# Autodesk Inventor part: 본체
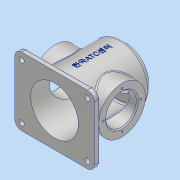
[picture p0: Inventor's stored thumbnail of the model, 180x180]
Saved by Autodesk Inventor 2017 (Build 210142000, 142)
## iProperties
Part Number: 본체
Material: 알루미늄 6061
Document SubType Name: Modeling
Designer: MRC
Density: 2.7 g/cm^3
Appearance: 알루미늄 - 평지
Mass: 1232.9 g
Surface Area: 1063.64 cm^2
Volume: 456.631 cm^3
Author: MRC
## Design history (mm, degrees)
sketch "스케치1"
  geometry: C1 r 50 at (0, 0); 1 further point
  constraints: 1 centre point, 1 coincident
  dimensions: "d0" = 100 diameter of C1
extrude "돌출1" new body sketch "스케치1" stored distance "d1" = 120; taper "d2" = 0 deg
sketch "스케치2"
  geometry: C1 r 41 at (0, 0); 1 further point
  constraints: 1 centre point, 1 coincident
  dimensions: "d3" = 82 diameter of C1
extrude "돌출2" join sketch "스케치2" distance "d4" = 5; taper "d5" = 0 deg
sketch "스케치3"
  geometry: L1 (70, -60)-(-70, -60); L2 (-70, -60)-(-70, 60); L3 (-70, 60)-(70, 60); L4 (70, 60)-(70, -60); L5 (70, -60)-(-70, 60); L6 (-70, -60)-(70, 60); 1 further point
  constraints: 12 end point, 2 midpoint, 2 parallel, 1 horizontal, 1 perpendicular
  dimensions: "d6" = 140 distance of L2.end L3.end; "d7" = 120 distance of L1.end L2.end
extrude "돌출3" join sketch "스케치3" distance "d8" = 10; taper "d9" = 0 deg
node "작업 평면1"
sketch "스케치4"
  geometry: C1 r 41 at (0, 0); 1 further point
  constraints: 1 centre point, 1 coincident
  dimensions: "d11" = 82 diameter of C1
extrude "돌출4" join sketch "스케치4" stored distance "d12" = 10; taper "d13" = 0 deg
sketch "스케치5"
  geometry: C1 r 42 at (0, 0); 1 further point
  constraints: 1 centre point, 1 coincident
  dimensions: "d14" = 84 diameter of C1
extrude "돌출5" cut sketch "스케치5" distance "d15" = 112; taper "d16" = 0 deg
sketch "스케치6"
  geometry: C1 r 27 at (0, 0); 1 further point
  constraints: 1 centre point, 1 coincident
  dimensions: "d17" = 54 diameter of C1
extrude "돌출6" cut sketch "스케치6" distance "d18" = 13; taper "d19" = 0 deg
sketch "스케치7"
  geometry: 2 further points
  constraints: 1 horizontal alignment
  dimensions: "d20" = 33 distance of point (0, 0) point (-33, 0)
hole "구멍1" sketch "스케치7" at (-33, 0) diameter "d21" = 3.242; stored, may be unused: countersink angle "d25" = 90 deg, drill point angle "d27" = 118 deg; dims "d22" = 8, "d23" = 4, "d24" = 2, "d26" = 10
sketch "스케치8"
  geometry: 2 further points
  constraints: 1 vertical alignment
  dimensions: "d28" = 33 distance of point (0, 0) point (0, 33)
hole "구멍2" sketch "스케치8" at (0, 33) diameter "d29" = 3.242; stored, may be unused: countersink angle "d33" = 90 deg, drill point angle "d35" = 118 deg; dims "d30" = 8, "d31" = 4, "d32" = 2, "d34" = 10
sketch "스케치9"
  geometry: C1 r 27 at (0, 0); 1 further point
  constraints: 1 centre point, 1 coincident
  dimensions: "d36" = 54 diameter of C1
extrude "돌출7" cut sketch "스케치9" stored distance "d37" = 13; taper "d38" = 0 deg
chamfer "모따기1" distance "d45" = 2; stored, may be unused: second distance "d46" = 2, angle "d47" = 45 deg
fillet "모깎기1" dims "d48" = 12
fillet "모깎기2" dims "d49" = 3
fillet "모깎기3" dims "d50" = 6
fillet "모깎기4" dims "d51" = 3
node "작업 평면2"
sketch "스케치10"
  geometry: L1 (-58, -60)-(58, -60) reference; 2 further points
  constraints: 1 vertical alignment, 1 other
  dimensions: "d53" = 66 distance from line of point (0, 6) L1
feature "엠보싱1" sketch "스케치10" dims "d11" = 82, "d54" = 0.5, "d55" = 0
sketch "스케치11"
  geometry: C1 r 4.5 at (-58, 48); A1 r 12 centre (-58, 48) between (-58, 60) and (-70, 48) reference; 1 further point
  constraints: 1 centre point, 1 concentric
  dimensions: "d56" = 9 diameter of C1
extrude "돌출8" cut sketch "스케치11" stored distance "d57" = 13; taper "d58" = 0 deg
node "솔리드1"
pattern_circular "원형 패턴1" dims angle "d40" = 360 deg
pattern_circular "원형 패턴2" dims angle "d43" = 360 deg
mirror "미러1"
mirror "미러2"
mirror "미러3"
other parameters: "d10" = 59
